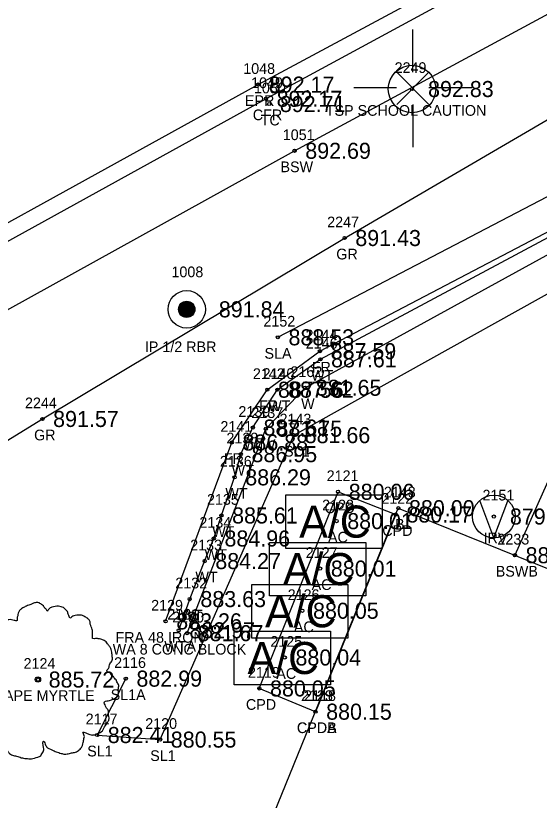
# Model space of a CAD drawing. Extents: x 1622501 to 1626664, y 1117816 to 1121579.
# Drawn here: x 1623346.8 to 1623395.8, y 1118647.2 to 1118720.5 of the extents above; entities that cross this region are included whole.
import ezdxf

# ---------------------------------------------------------------- set-up
doc = ezdxf.new("R2010")
doc.units = 0
for name, color, linetype in [('RD_EX_Bldg', 7, 'Continuous'), ('RD_EX_Bldg_txCode', 7, 'Continuous'), ('RD_EX_BldgApp', 7, 'Continuous'), ('RD_EX_BldgApp_txCode', 7, 'Continuous'), ('RD_EX_Conc', 7, 'Continuous'), ('RD_EX_Conc_txCode', 7, 'Continuous'), ('RD_EX_DV_Prop_txCode', 7, 'Continuous'), ('RD_EX_DV_PropPin', 7, 'Continuous'), ('RD_EX_Fence_Other', 7, 'Continuous'), ('RD_EX_Fence_Other_txCode', 7, 'Continuous'), ('RD_EX_GuardRail', 7, 'Continuous'), ('RD_EX_GuardRail_txCode', 7, 'Continuous'), ('RD_EX_Misc', 7, 'Continuous'), ('RD_EX_Misc_txCode', 7, 'Continuous'), ('RD_EX_Road', 7, 'Continuous'), ('RD_EX_Road_txCode', 7, 'Continuous'), ('RD_EX_SU_Pole', 7, 'Continuous'), ('RD_EX_TX_Bldg_ELEV', 7, 'Continuous'), ('RD_EX_TX_BldgApp_ELEV', 7, 'Continuous'), ('RD_EX_TX_Conc_ELEV', 7, 'Continuous'), ('RD_EX_TX_DV_Prop_ELEV', 7, 'Continuous'), ('RD_EX_TX_Fence_Other_ELEV', 7, 'Continuous'), ('RD_EX_TX_GuardRail_ELEV', 7, 'Continuous'), ('RD_EX_TX_Misc_ELEV', 7, 'Continuous'), ('RD_EX_TX_Road_ELEV', 7, 'Continuous'), ('RD_EX_TX_UT_ELEV', 7, 'Continuous'), ('RD_EX_TX_VEG_ELEV', 7, 'Continuous'), ('RD_EX_UT_txCode', 7, 'Continuous'), ('RD_EX_VEG', 7, 'Continuous'), ('RD_EX_VEG_txCode', 7, 'Continuous'), ('RD_SMD_Locator', 7, 'Continuous')]:
    doc.layers.add(name, color=color, linetype=linetype)

msp = doc.modelspace()

# ---------------------------------------------------------------- linework, layer by layer
at = {"layer": 'RD_EX_Bldg'}
msp.add_lwpolyline([(1623351.424, 1118597.995), (1623382.58, 1118674.507), (1623433.654, 1118653.895), (1623402.498, 1118577.383), (1623351.424, 1118597.995)], dxfattribs=at)
at = {"layer": 'RD_EX_BldgApp'}
for q in [(1623390.209, 1118675.213), (1623392.834, 1118675.176)]:
    msp.add_line((1623391.512, 1118671.73), q, dxfattribs=at)
msp.add_lwpolyline([(1623362.832, 1118662.827), (1623370.193, 1118681.931), (1623373.866, 1118685.757), (1623410.694, 1118705.967), (1623459.429, 1118733.933), (1623484.083, 1118750.076), (1623515.96, 1118771.434)], dxfattribs=at)
for points in [[(1623372.07, 1118670.743), (1623372.07, 1118675.743), (1623381.07, 1118675.743), (1623381.07, 1118670.743)], [(1623370.54, 1118666.308), (1623370.54, 1118671.308), (1623379.54, 1118671.308), (1623379.54, 1118666.308)], [(1623368.876, 1118662.37), (1623368.876, 1118667.37), (1623377.876, 1118667.37), (1623377.876, 1118662.37)], [(1623367.234, 1118658.001), (1623367.234, 1118663.001), (1623376.234, 1118663.001), (1623376.234, 1118658.001)]]:
    msp.add_lwpolyline(points, close=True, dxfattribs=at)
for radius in [2, 0.15]:
    msp.add_circle((1623391.512, 1118673.723), radius, dxfattribs=at)
at = {"layer": 'RD_EX_Conc'}
for points in [[(1623283.761, 1118664.167), (1623326.745, 1118688.794), (1623370.205, 1118712.758), (1623413.974, 1118736.474), (1623457.083, 1118761.617), (1623498.83, 1118789.052), (1623539.225, 1118818.399), (1623578.605, 1118849.246), (1623610.287, 1118876.06), (1623617.2, 1118880.675), (1623627.78, 1118883.825), (1623633.909, 1118884.567), (1623640.773, 1118884.032), (1623649.389, 1118881.534), (1623656.998, 1118877.662), (1623663.674, 1118871.908), (1623688.617, 1118845.058), (1623694.116, 1118836.37)], [(1623287.102, 1118659.692), (1623329.453, 1118683.877), (1623372.881, 1118707.9), (1623416.572, 1118731.516), (1623459.835, 1118756.855), (1623502.097, 1118784.616), (1623542.536, 1118813.857), (1623581.966, 1118844.894), (1623613.887, 1118871.887), (1623619.415, 1118875.421), (1623623.688, 1118876.741), (1623623.459, 1118877.275), (1623631.268, 1118878.694), (1623634.056, 1118878.854), (1623639.628, 1118878.454), (1623640.557, 1118883.374)], [(1623458.019, 1118694.702), (1623453.469, 1118696.574), (1623443.082, 1118671.009), (1623439.137, 1118661.507), (1623397.246, 1118678.511), (1623393.478, 1118670.109)], [(1623374.836, 1118655.489), (1623369.587, 1118657.662), (1623376.946, 1118676.036), (1623382.338, 1118673.915), (1623374.836, 1118655.489)]]:
    msp.add_lwpolyline(points, dxfattribs=at)
at = {"layer": 'RD_EX_DV_PropPin'}
for p, q in [((1623362.063, 1118692.888), (1623362.063, 1118693.28)), ((1623362.098, 1118692.786), (1623362.098, 1118693.382)), ((1623362.133, 1118692.715), (1623362.133, 1118693.454)), ((1623362.168, 1118692.658), (1623362.168, 1118693.511)), ((1623362.203, 1118692.61), (1623362.203, 1118693.558)), ((1623362.238, 1118692.569), (1623362.238, 1118693.599)), ((1623362.273, 1118692.534), (1623362.273, 1118693.635)), ((1623362.308, 1118692.502), (1623362.308, 1118693.666)), ((1623362.343, 1118692.474), (1623362.343, 1118693.694)), ((1623362.379, 1118692.45), (1623362.379, 1118693.719)), ((1623362.414, 1118692.428), (1623362.414, 1118693.741)), ((1623362.449, 1118692.409), (1623362.449, 1118693.76)), ((1623362.484, 1118692.392), (1623362.484, 1118693.777)), ((1623362.519, 1118692.377), (1623362.519, 1118693.792)), ((1623362.554, 1118692.364), (1623362.554, 1118693.805)), ((1623362.589, 1118692.353), (1623362.589, 1118693.816)), ((1623362.624, 1118692.344), (1623362.624, 1118693.825)), ((1623362.659, 1118692.336), (1623362.659, 1118693.832)), ((1623362.694, 1118692.331), (1623362.694, 1118693.838)), ((1623362.729, 1118692.327), (1623362.729, 1118693.842)), ((1623362.764, 1118692.324), (1623362.764, 1118693.845)), ((1623362.799, 1118692.323), (1623362.799, 1118693.845)), ((1623362.834, 1118692.324), (1623362.834, 1118693.845)), ((1623362.869, 1118692.327), (1623362.869, 1118693.842)), ((1623362.904, 1118692.331), (1623362.904, 1118693.838)), ((1623362.939, 1118692.336), (1623362.939, 1118693.832)), ((1623362.974, 1118692.344), (1623362.974, 1118693.825)), ((1623363.009, 1118692.353), (1623363.009, 1118693.816)), ((1623363.044, 1118692.364), (1623363.044, 1118693.805)), ((1623363.079, 1118692.377), (1623363.079, 1118693.792)), ((1623363.114, 1118692.392), (1623363.114, 1118693.777)), ((1623363.149, 1118692.409), (1623363.149, 1118693.76)), ((1623363.184, 1118692.428), (1623363.184, 1118693.741)), ((1623363.219, 1118692.45), (1623363.219, 1118693.719)), ((1623363.254, 1118692.474), (1623363.254, 1118693.694)), ((1623363.289, 1118692.502), (1623363.289, 1118693.666)), ((1623363.324, 1118692.534), (1623363.324, 1118693.635)), ((1623363.359, 1118692.569), (1623363.359, 1118693.599)), ((1623363.394, 1118692.61), (1623363.394, 1118693.558)), ((1623363.429, 1118692.658), (1623363.429, 1118693.511)), ((1623363.464, 1118692.715), (1623363.464, 1118693.454)), ((1623363.499, 1118692.786), (1623363.499, 1118693.382)), ((1623363.534, 1118692.888), (1623363.534, 1118693.28))]:
    msp.add_line(p, q, dxfattribs=at)
for radius in [1.75, 0.761]:
    msp.add_circle((1623362.799, 1118693.084), radius, dxfattribs=at)
at = {"layer": 'RD_EX_Fence_Other'}
msp.add_lwpolyline([(1623360.82, 1118663.932), (1623367.011, 1118680.639), (1623370.331, 1118685.573), (1623375.249, 1118689.174), (1623407.361, 1118706.001), (1623425.619, 1118716.341), (1623480.358, 1118749.66), (1623515.549, 1118772.603)], dxfattribs=at)
at = {"layer": 'RD_EX_GuardRail'}
msp.add_lwpolyline([(1623328.796, 1118667.195), (1623333.583, 1118673.211), (1623349.309, 1118682.841), (1623377.56, 1118699.748), (1623423.094, 1118726.327), (1623463.83, 1118751.666), (1623511.133, 1118780.414)], dxfattribs=at)
at = {"layer": 'RD_EX_Misc'}
msp.add_lwpolyline([(1623362.047, 1118663.092), (1623363.077, 1118666.011), (1623364.471, 1118669.561), (1623365.33, 1118671.673), (1623366.043, 1118673.822), (1623367.273, 1118677.387), (1623367.858, 1118679.553), (1623368.979, 1118682.037), (1623371.277, 1118685.581), (1623375.298, 1118688.415), (1623407.747, 1118705.764), (1623425.855, 1118715.821), (1623458.998, 1118735.378), (1623483.907, 1118751.097), (1623484.139, 1118751.024), (1623515.704, 1118772.555)], dxfattribs=at)
at = {"layer": 'RD_EX_Road'}
msp.add_lwpolyline([(1623282.988, 1118665.294), (1623326.108, 1118690.168), (1623369.47, 1118714.084), (1623413.312, 1118737.635), (1623456.355, 1118762.797), (1623498.01, 1118790.21), (1623538.412, 1118819.484), (1623577.719, 1118850.337), (1623609.415, 1118877.294), (1623616.689, 1118881.904), (1623627.606, 1118885.26), (1623634.056, 1118885.78), (1623640.822, 1118885.362), (1623649.781, 1118882.397), (1623657.444, 1118878.352), (1623664.357, 1118872.554), (1623689.274, 1118845.674), (1623694.989, 1118836.791)], dxfattribs=at)
at = {"layer": 'RD_EX_SU_Pole'}
for p, q in [((1623383.932, 1118715.237), (1623383.932, 1118719.237)), ((1623385.432, 1118715.237), (1623382.432, 1118712.237)), ((1623382.432, 1118715.237), (1623385.432, 1118712.237)), ((1623385.446, 1118713.803), (1623389.462, 1118713.803)), ((1623382.407, 1118713.785), (1623378.407, 1118713.785)), ((1623383.932, 1118712.237), (1623383.932, 1118708.237))]:
    msp.add_line(p, q, dxfattribs=at)
msp.add_circle((1623383.864, 1118713.67), 2.217, dxfattribs=at)
at = {"layer": 'RD_EX_VEG'}
for points in [[(1623371.315, 1118690.471), (1623410.924, 1118711.122), (1623478.591, 1118750.831), (1623514.185, 1118775.518)], [(1623357.099, 1118658.576), (1623354.417, 1118653.307), (1623360.309, 1118652.881), (1623372.824, 1118681.33), (1623408.505, 1118701.188), (1623470.644, 1118735.679), (1623505.961, 1118762.905)]]:
    msp.add_lwpolyline(points, dxfattribs=at)
for centre, radius in [((1623348.89, 1118658.493), 0.25), ((1623348.877, 1118658.474), 0.0001)]:
    msp.add_circle(centre, radius, dxfattribs=at)
for points in [[(1623349.022, 1118665.66), (1623348.722, 1118665.685), (1623348.397, 1118665.585), (1623348.147, 1118665.485), (1623347.922, 1118665.41), (1623347.698, 1118665.31), (1623347.398, 1118665.135), (1623347.173, 1118664.935), (1623347.048, 1118664.685), (1623346.998, 1118664.46), (1623346.948, 1118664.186), (1623346.948, 1118664.011), (1623346.823, 1118663.986), (1623346.673, 1118664.011), (1623346.423, 1118664.086), (1623346.173, 1118664.086), (1623345.923, 1118664.086), (1623345.573, 1118664.061), (1623345.224, 1118664.061), (1623344.949, 1118664.011), (1623344.624, 1118663.961), (1623344.249, 1118663.836), (1623343.899, 1118663.711), (1623343.599, 1118663.461), (1623343.349, 1118662.986), (1623343.224, 1118662.636), (1623343.075, 1118662.386), (1623343.224, 1118661.937), (1623343.399, 1118661.587), (1623343.424, 1118661.387), (1623343.499, 1118660.962), (1623343.599, 1118660.737), (1623343.724, 1118660.537), (1623343.649, 1118660.512), (1623343.274, 1118660.462), (1623342.975, 1118660.362), (1623342.55, 1118660.137), (1623342.325, 1118659.912), (1623342.225, 1118659.588), (1623342.2, 1118659.238), (1623342.1, 1118659.038), (1623342.025, 1118658.763), (1623342, 1118658.688), (1623341.95, 1118658.363), (1623342.05, 1118657.913), (1623342.075, 1118657.563), (1623342.2, 1118657.339), (1623342.35, 1118657.164), (1623342.525, 1118656.914), (1623342.925, 1118656.689), (1623343.249, 1118656.589), (1623343.449, 1118656.564), (1623343.274, 1118656.064), (1623343.224, 1118655.714), (1623343.1, 1118655.314), (1623343.1, 1118655.24), (1623343.05, 1118654.765), (1623343.199, 1118654.44), (1623343.274, 1118654.065), (1623343.449, 1118653.84), (1623343.724, 1118653.54), (1623344.049, 1118653.315), (1623344.549, 1118653.19), (1623344.949, 1118653.215), (1623345.524, 1118653.39), (1623345.773, 1118653.465), (1623345.748, 1118653.29), (1623345.773, 1118652.915), (1623345.773, 1118652.491), (1623345.923, 1118652.166), (1623346.023, 1118651.891), (1623346.173, 1118651.641), (1623346.498, 1118651.416), (1623346.898, 1118651.341), (1623347.323, 1118651.191), (1623347.773, 1118651.116), (1623348.272, 1118651.091), (1623348.872, 1118651.241), (1623349.147, 1118651.366), (1623349.247, 1118651.541), (1623349.447, 1118651.916), (1623349.397, 1118652.141), (1623349.422, 1118652.741), (1623349.522, 1118652.566), (1623349.697, 1118652.216), (1623350.196, 1118651.916), (1623350.596, 1118651.741), (1623351.071, 1118651.591), (1623351.371, 1118651.516), (1623351.846, 1118651.591), (1623352.221, 1118651.666), (1623352.595, 1118651.791), (1623352.895, 1118652.066), (1623353.07, 1118652.341), (1623353.12, 1118652.616), (1623353.195, 1118652.99), (1623353.245, 1118653.165)], [(1623353.245, 1118653.165), (1623353.17, 1118653.34), (1623353.12, 1118653.59), (1623353.195, 1118653.565), (1623353.37, 1118653.515), (1623353.645, 1118653.39), (1623353.87, 1118653.315), (1623354.195, 1118653.34), (1623354.47, 1118653.44), (1623354.919, 1118653.715), (1623355.194, 1118654.19), (1623355.469, 1118654.59), (1623355.544, 1118654.915), (1623355.494, 1118655.14), (1623355.469, 1118655.639), (1623355.269, 1118655.889), (1623355.219, 1118656.014), (1623355.119, 1118656.414), (1623355.194, 1118656.464), (1623355.469, 1118656.514), (1623355.844, 1118656.639), (1623356.119, 1118656.764), (1623356.344, 1118656.939), (1623356.419, 1118657.164), (1623356.394, 1118657.563), (1623356.444, 1118657.963), (1623356.369, 1118658.113), (1623356.269, 1118658.263), (1623356.194, 1118658.463), (1623356.044, 1118658.613), (1623355.944, 1118658.763), (1623355.844, 1118658.863), (1623355.719, 1118659.013), (1623355.544, 1118659.138), (1623355.394, 1118659.188), (1623355.344, 1118659.338), (1623355.494, 1118659.538), (1623355.544, 1118659.638), (1623355.569, 1118659.862), (1623355.794, 1118660.212), (1623355.844, 1118660.612), (1623355.794, 1118661.037), (1623355.744, 1118661.312), (1623355.594, 1118661.587), (1623355.394, 1118661.837), (1623355.269, 1118662.012), (1623355.094, 1118662.136), (1623354.769, 1118662.261), (1623354.52, 1118662.311), (1623354.17, 1118662.311), (1623353.97, 1118662.361), (1623353.995, 1118662.411), (1623353.995, 1118662.561), (1623353.995, 1118662.836), (1623353.92, 1118663.286), (1623353.77, 1118663.786), (1623353.77, 1118663.811), (1623353.67, 1118664.061), (1623353.445, 1118664.261), (1623353.27, 1118664.36), (1623353.07, 1118664.485), (1623352.82, 1118664.51), (1623352.52, 1118664.51), (1623352.246, 1118664.46), (1623352.046, 1118664.36), (1623351.871, 1118664.236), (1623351.796, 1118664.385), (1623351.696, 1118664.685), (1623351.646, 1118664.835), (1623351.496, 1118665.01), (1623351.271, 1118665.21), (1623350.821, 1118665.335), (1623350.196, 1118665.26), (1623349.897, 1118665.06), (1623349.747, 1118664.885), (1623349.697, 1118665.01), (1623349.497, 1118665.21), (1623349.397, 1118665.385), (1623349.222, 1118665.51), (1623349.072, 1118665.61), (1623348.972, 1118665.66)]]:
    msp.add_spline(points, degree=3, dxfattribs=at)
at = {"layer": 'RD_SMD_Locator'}
for centre in [(1623369.47, 1118714.084), (1623383.864, 1118713.67), (1623370.205, 1118712.758), (1623370.507, 1118712.269), (1623372.881, 1118707.9), (1623377.56, 1118699.748), (1623362.799, 1118693.084), (1623371.315, 1118690.471), (1623375.249, 1118689.174), (1623375.298, 1118688.415), (1623370.331, 1118685.573), (1623371.277, 1118685.581), (1623373.866, 1118685.757), (1623349.309, 1118682.841), (1623368.979, 1118682.037), (1623370.193, 1118681.931), (1623372.824, 1118681.33), (1623367.011, 1118680.639), (1623367.858, 1118679.553), (1623367.273, 1118677.387), (1623376.946, 1118676.036), (1623382.58, 1118674.507), (1623366.043, 1118673.822), (1623382.338, 1118673.915), (1623376.805, 1118673.295), (1623365.33, 1118671.673), (1623393.478, 1118670.109), (1623364.471, 1118669.561), (1623375.275, 1118668.859), (1623363.077, 1118666.011), (1623373.61, 1118664.921), (1623360.82, 1118663.932), (1623362.047, 1118663.092), (1623362.832, 1118662.827), (1623371.968, 1118660.553), (1623348.89, 1118658.493), (1623357.099, 1118658.576), (1623369.587, 1118657.662), (1623374.836, 1118655.489), (1623374.836, 1118655.489), (1623354.417, 1118653.307), (1623360.309, 1118652.881)]:
    msp.add_circle(centre, 0.15, dxfattribs=at)

# ---------------------------------------------------------------- texts
at = {"layer": 'RD_EX_Bldg_txCode'}
for s, p in [('2148', (1623381.233, 1118675.507)), ('B', (1623382.272, 1118672.507))]:
    msp.add_text(s, height=1, dxfattribs=at).set_placement(p)
at = {"layer": 'RD_EX_BldgApp'}
for p in [(1623373.316, 1118671.747), (1623371.786, 1118667.311), (1623370.122, 1118663.373), (1623368.479, 1118659.005)]:
    msp.add_text('A/C', height=3, dxfattribs=at).set_placement(p)
at = {"layer": 'RD_EX_BldgApp_txCode'}
for s, p in [('2128', (1623375.458, 1118674.295)), ('AC', (1623376.009, 1118671.295)), ('2127', (1623373.928, 1118669.859)), ('AC', (1623374.48, 1118666.859)), ('2126', (1623372.24, 1118665.921)), ('AC', (1623372.815, 1118662.921)), ('2125', (1623370.622, 1118661.553)), ('AC', (1623371.173, 1118658.553))]:
    msp.add_text(s, height=1, dxfattribs=at).set_placement(p)
at = {"layer": 'RD_EX_Conc_txCode'}
for s, p in [('1049', (1623368.819, 1118713.758)), ('1050', (1623369.082, 1118713.269)), ('CFR', (1623368.977, 1118710.758)), ('TC', (1623369.712, 1118710.269)), ('1051', (1623371.778, 1118708.9)), ('BSW', (1623371.566, 1118705.9)), ('2121', (1623375.883, 1118677.036)), ('2122', (1623380.992, 1118674.915)), ('CPD', (1623375.694, 1118674.036)), ('CPD', (1623381.086, 1118671.915)), ('2233', (1623391.848, 1118671.109)), ('BSWB', (1623391.691, 1118668.109)), ('2119', (1623368.524, 1118658.662)), ('2123', (1623373.489, 1118656.489)), ('2118', (1623373.773, 1118656.489)), ('CPD', (1623368.335, 1118655.662)), ('CPDA', (1623373.095, 1118653.489)), ('CPDB', (1623373.111, 1118653.489))]:
    msp.add_text(s, height=1, dxfattribs=at).set_placement(p)
at = {"layer": 'RD_EX_DV_Prop_txCode'}
for s, p in [('1008', (1623361.374, 1118696.084)), ('IP 1/2 RBR', (1623358.885, 1118689.084))]:
    msp.add_text(s, height=1, dxfattribs=at).set_placement(p)
at = {"layer": 'RD_EX_Fence_Other_txCode'}
for s, p in [('2144', (1623373.903, 1118690.174)), ('FR', (1623374.493, 1118687.174)), ('2142', (1623368.984, 1118686.573)), ('FR', (1623369.575, 1118683.573)), ('2141', (1623365.948, 1118681.639)), ('FR', (1623366.255, 1118678.639)), ('2129', (1623359.473, 1118664.932)), ('FRA 48 IRON', (1623356.142, 1118661.932))]:
    msp.add_text(s, height=1, dxfattribs=at).set_placement(p)
at = {"layer": 'RD_EX_GuardRail_txCode'}
for s, p in [('2247', (1623375.93, 1118700.748)), ('GR', (1623376.78, 1118697.748)), ('2244', (1623347.679, 1118683.841)), ('GR', (1623348.53, 1118680.841))]:
    msp.add_text(s, height=1, dxfattribs=at).set_placement(p)
at = {"layer": 'RD_EX_Misc_txCode'}
for s, p in [('2146', (1623373.928, 1118689.415)), ('2140', (1623369.892, 1118686.581)), ('2162', (1623372.496, 1118686.757)), ('WT', (1623374.439, 1118686.415)), ('WT', (1623370.419, 1118683.581)), ('W', (1623373.496, 1118683.757)), ('2139', (1623367.632, 1118683.037)), ('2137', (1623368.846, 1118682.931)), ('2138', (1623366.511, 1118680.553)), ('WT', (1623368.12, 1118680.037)), ('W', (1623369.823, 1118679.931)), ('2136', (1623365.903, 1118678.387)), ('WT', (1623366.999, 1118677.553)), ('2135', (1623364.696, 1118674.822)), ('WT', (1623366.415, 1118675.387)), ('2151', (1623390.449, 1118675.223)), ('2134', (1623363.983, 1118672.673)), ('WT', (1623365.184, 1118671.822)), ('IRV', (1623390.552, 1118671.223)), ('2133', (1623363.125, 1118670.561)), ('WT', (1623364.472, 1118669.673)), ('WT', (1623363.613, 1118667.561)), ('2132', (1623361.731, 1118667.011)), ('2131', (1623360.984, 1118664.092)), ('2130', (1623361.446, 1118663.827)), ('WT', (1623362.219, 1118664.011)), ('WA 8 CONC BLOCK', (1623355.879, 1118660.827)), ('WTA', (1623360.701, 1118661.092))]:
    msp.add_text(s, height=1, dxfattribs=at).set_placement(p)
at = {"layer": 'RD_EX_Road_txCode'}
for s, p in [('1048', (1623368.084, 1118715.084)), ('EPR', (1623368.242, 1118712.084))]:
    msp.add_text(s, height=1, dxfattribs=at).set_placement(p)
at = {"layer": 'RD_EX_TX_Bldg_ELEV'}
msp.add_text('880.00', height=1.5, dxfattribs=at).set_placement((1623383.58, 1118673.757))
at = {"layer": 'RD_EX_TX_BldgApp_ELEV'}
for s, p in [('880.01', (1623377.805, 1118672.545)), ('880.01', (1623376.275, 1118668.109)), ('880.05', (1623374.61, 1118664.171)), ('880.04', (1623372.968, 1118659.803))]:
    msp.add_text(s, height=1.5, dxfattribs=at).set_placement(p)
at = {"layer": 'RD_EX_TX_Conc_ELEV'}
for s, p in [('892.17', (1623371.205, 1118712.008)), ('892.71', (1623371.507, 1118711.519)), ('892.69', (1623373.881, 1118707.15)), ('880.06', (1623377.946, 1118675.286)), ('880.17', (1623383.338, 1118673.165)), ('880.14', (1623394.478, 1118669.359)), ('880.05', (1623370.587, 1118656.912)), ('880.15', (1623375.836, 1118654.739)), ('880.15', (1623375.836, 1118654.739))]:
    msp.add_text(s, height=1.5, dxfattribs=at).set_placement(p)
at = {"layer": 'RD_EX_TX_DV_Prop_ELEV'}
msp.add_text('891.84', height=1.5, dxfattribs=at).set_placement((1623365.799, 1118692.334))
at = {"layer": 'RD_EX_TX_Fence_Other_ELEV'}
for s, p in [('887.59', (1623376.249, 1118688.424)), ('887.56', (1623371.331, 1118684.823)), ('886.88', (1623368.011, 1118679.889)), ('883.26', (1623361.82, 1118663.182))]:
    msp.add_text(s, height=1.5, dxfattribs=at).set_placement(p)
at = {"layer": 'RD_EX_TX_GuardRail_ELEV'}
for s, p in [('891.43', (1623378.56, 1118698.998)), ('891.57', (1623350.309, 1118682.091))]:
    msp.add_text(s, height=1.5, dxfattribs=at).set_placement(p)
at = {"layer": 'RD_EX_TX_Misc_ELEV'}
for s, p in [('887.61', (1623376.298, 1118687.665)), ('887.62', (1623372.277, 1118684.831)), ('881.65', (1623374.866, 1118685.007)), ('887.61', (1623369.979, 1118681.287)), ('881.75', (1623371.193, 1118681.181)), ('886.95', (1623368.858, 1118678.803)), ('886.29', (1623368.273, 1118676.637)), ('885.61', (1623367.043, 1118673.072)), ('879.80', (1623393.012, 1118672.973)), ('884.96', (1623366.33, 1118670.923)), ('884.27', (1623365.471, 1118668.811)), ('883.63', (1623364.077, 1118665.261)), ('882.97', (1623363.047, 1118662.342)), ('881.67', (1623363.832, 1118662.077))]:
    msp.add_text(s, height=1.5, dxfattribs=at).set_placement(p)
at = {"layer": 'RD_EX_TX_Road_ELEV'}
msp.add_text('892.17', height=1.5, dxfattribs=at).set_placement((1623370.47, 1118713.334))
at = {"layer": 'RD_EX_TX_UT_ELEV'}
msp.add_text('892.83', height=1.5, dxfattribs=at).set_placement((1623385.364, 1118712.92))
at = {"layer": 'RD_EX_TX_VEG_ELEV'}
for s, p in [('888.53', (1623372.315, 1118689.721)), ('881.66', (1623373.824, 1118680.58)), ('885.72', (1623349.89, 1118657.743)), ('882.99', (1623358.099, 1118657.826)), ('882.41', (1623355.417, 1118652.557)), ('880.55', (1623361.309, 1118652.131))]:
    msp.add_text(s, height=1.5, dxfattribs=at).set_placement(p)
at = {"layer": 'RD_EX_UT_txCode'}
for s, p in [('2249', (1623382.234, 1118715.17)), ('TSP SCHOOL CAUTION', (1623375.801, 1118711.17))]:
    msp.add_text(s, height=1, dxfattribs=at).set_placement(p)
at = {"layer": 'RD_EX_VEG_txCode'}
for s, p in [('2152', (1623369.968, 1118691.471)), ('SLA', (1623370.071, 1118688.471)), ('2143', (1623371.478, 1118682.33)), ('SL1', (1623371.903, 1118679.33)), ('2124', (1623347.544, 1118659.493)), ('2116', (1623356.013, 1118659.576)), ('T 4 CRAPE MYRTLE', (1623341.484, 1118656.493)), ('SL1A', (1623355.69, 1118656.576)), ('2117', (1623353.354, 1118654.307)), ('2120', (1623358.923, 1118653.881)), ('SL1', (1623353.496, 1118651.307)), ('SL1', (1623359.388, 1118650.881))]:
    msp.add_text(s, height=1, dxfattribs=at).set_placement(p)

doc.saveas('drawing.dxf')
